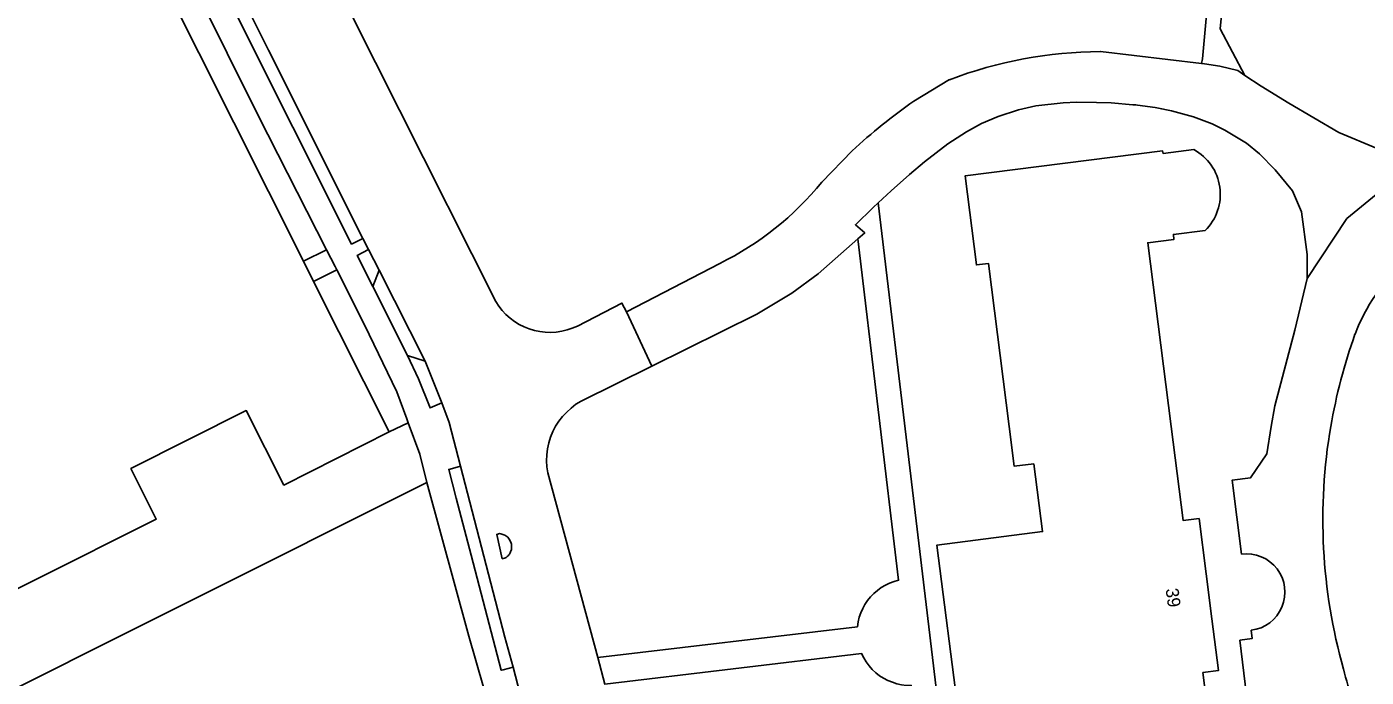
# Model space of a CAD drawing. Extents: x 158132 to 159664, y 385256 to 387218.
# Drawn here: x 159064.7 to 159168.9, y 386480.5 to 386531.1 of the extents above; entities that cross this region are included whole.
import ezdxf

# ---------------------------------------------------------------- set-up
doc = ezdxf.new("R2010")
doc.units = 0
for name, color, linetype in [('IMGEO_Berm_groen', 7, 'Continuous'), ('IMGEO_Groenvoorziening', 7, 'Continuous'), ('IMGEO_Loofbos', 7, 'Continuous'), ('IMGEO_Pand', 7, 'Continuous'), ('IMGEO_Pand_nummerreeks', 7, 'Continuous'), ('IMGEO_Parkeervlak_open', 7, 'Continuous'), ('IMGEO_Rijbaan_lokaal_gesloten', 7, 'Continuous'), ('IMGEO_Rijbaan_lokaal_open', 7, 'Continuous'), ('IMGEO_Verkeerseiland_gesloten', 7, 'Continuous'), ('IMGEO_Voetpad_open', 7, 'Continuous')]:
    doc.layers.add(name, color=color, linetype=linetype)

msp = doc.modelspace()

# ---------------------------------------------------------------- linework, layer by layer
at = {"layer": 'IMGEO_Berm_groen'}
for points in [[(159083.47, 386529.31), (159081.68, 386532.89), (159080.81, 386532.42), (159089.95, 386514.21), (159090.83, 386514.64)], [(159091.26, 386513.79), (159090.38, 386513.33), (159091.61, 386510.9), (159092.08, 386512.17)], [(159095.67, 386505.1), (159094.3, 386505.54), (159095.16, 386503.71), (159096.05, 386501.45), (159096.98, 386501.85)], [(159098.43, 386496.92), (159097.63, 386496.69), (159097.51, 386496.66), (159098.09, 386494.42), (159099.25, 386489.99), (159101.6, 386481.01), (159101.74, 386481.06), (159102.52, 386481.25), (159101.87, 386483.6)]]:
    msp.add_lwpolyline(points, close=True, dxfattribs=at)
at = {"layer": 'IMGEO_Groenvoorziening'}
for points in [[(159148.23, 386529.21), (159156.1, 386528.28), (159156.17, 386528.64), (159157.04, 386538.09), (159157.3, 386540.4), (159141.76, 386542.14), (159126.49, 386544.29), (159130.01, 386573.65), (159146.27, 386576.84)], [(159086.18, 386539.58), (159101.17, 386509.73), (159101.4, 386509.38), (159101.67, 386509.04), (159101.96, 386508.73), (159102.28, 386508.44), (159102.62, 386508.18), (159102.99, 386507.96), (159103.37, 386507.76), (159103.77, 386507.6), (159104.18, 386507.48), (159104.6, 386507.39), (159105.02, 386507.34), (159105.45, 386507.33), (159105.88, 386507.36), (159106.3, 386507.42), (159106.72, 386507.52), (159107.12, 386507.66), (159107.52, 386507.83), (159110.99, 386509.61), (159111.35, 386508.93), (159118.62, 386512.71)], [(159133.72, 386525.35), (159136.49, 386527.02)], [(159159.22, 386490.06), (159158.48, 386495.81), (159159.92, 386496.01), (159161.2, 386497.88), (159161.54, 386500), (159161.8, 386501.6), (159163.38, 386507.51), (159164.32, 386511.52), (159164.33, 386513.4), (159163.9, 386516.72), (159163.2, 386518.37), (159161.85, 386520), (159160.62, 386521.24), (159159.6, 386522.06), (159157.93, 386523.09), (159156.93, 386523.57), (159155.49, 386524.12), (159153.76, 386524.6), (159153.37, 386524.67), (159153.01, 386524.74), (159152.51, 386524.84), (159151.12, 386525.03), (159151, 386525.05), (159150.75, 386525.07), (159149.07, 386525.21), (159147.94, 386525.25), (159146.4, 386525.26), (159145.33, 386525.22), (159143.22, 386524.99), (159141.86, 386524.68), (159140.28, 386524.15), (159138.99, 386523.6), (159137.8, 386522.96), (159136.37, 386522.02), (159134.55, 386520.62), (159133.37, 386519.64), (159131.94, 386518.36), (159130.94, 386517.43), (159139.8, 386443.12)], [(159126.55, 386519.04), (159128.92, 386521.47)], [(159139.52, 386512.71), (159138.58, 386512.59), (159137.7, 386519.52), (159153.08, 386521.47), (159153.11, 386521.28), (159155.5, 386521.58)], [(159156.38, 386515.26), (159153.92, 386514.96), (159153.96, 386514.58), (159151.92, 386514.32), (159153.74, 386500), (159154.68, 386492.67), (159155.92, 386492.83), (159156.46, 386488.53), (159156.91, 386485.02), (159157.42, 386480.99), (159156.22, 386480.84), (159158.99, 386459.1), (159161.05, 386459.36), (159161.1, 386458.96), (159163.46, 386459.26)], [(159137.19, 386477.61), (159135.51, 386490.77), (159143.74, 386491.82), (159143.04, 386497.09), (159141.53, 386496.9), (159141.14, 386500), (159139.52, 386512.71)], [(159057.35, 386422.06), (159076.55, 386431.69), (159094.11, 386440.59), (159110.07, 386448.64), (159110.2, 386448.7), (159111.12, 386449.17), (159111.56, 386449.46), (159111.98, 386449.8), (159112.36, 386450.17), (159112.67, 386450.53), (159110.57, 386454.48), (159107.78, 386460.06), (159105.15, 386465.72), (159102.7, 386471.45), (159101.94, 386473.64), (159099.08, 386483.66), (159095.79, 386495.63), (159058.61, 386477.03)], [(159162.07, 386475.51), (159160.01, 386475.65), (159159.1, 386483.35), (159160.04, 386483.48), (159159.98, 386484.13)], [(159134.79, 386442.58), (159136.74, 386442.71), (159137.91, 386442.87), (159133.51, 386479.83), (159133.13, 386479.84), (159132.76, 386479.89), (159132.39, 386479.96), (159132.04, 386480.08), (159131.69, 386480.22), (159131.36, 386480.39), (159131.05, 386480.59), (159130.75, 386480.82), (159130.48, 386481.08), (159130.23, 386481.35), (159130.01, 386481.66), (159129.81, 386481.98), (159129.64, 386482.31), (159109.67, 386479.93)]]:
    msp.add_lwpolyline(points, dxfattribs=at)
for points in [[(159070.67, 386548.43), (159060.8, 386567.86), (159059.03, 386566.97), (159086.21, 386512.87), (159088, 386513.77), (159082.68, 386524.24)], [(159129.36, 386514.61), (159126.27, 386511.9), (159124.21, 386510.4), (159121.48, 386508.75), (159113.31, 386504.7), (159107.81, 386501.98), (159107.41, 386501.73), (159107.04, 386501.44), (159106.69, 386501.13), (159106.37, 386500.78), (159106.08, 386500.41), (159105.83, 386500.02), (159105.61, 386499.6), (159105.44, 386499.16), (159105.3, 386498.72), (159105.2, 386498.26), (159105.14, 386497.79), (159105.12, 386497.32), (159105.15, 386496.85), (159105.22, 386496.39), (159109.11, 386482.01), (159129.32, 386484.41), (159129.37, 386484.78), (159129.46, 386485.14), (159129.58, 386485.48), (159129.73, 386485.82), (159129.91, 386486.14), (159130.11, 386486.45), (159130.35, 386486.73), (159130.6, 386487), (159130.88, 386487.23), (159131.18, 386487.45), (159131.5, 386487.64), (159131.83, 386487.79), (159132.18, 386487.92), (159132.53, 386488.02)], [(159090.95, 386507.93), (159088.8, 386512.21), (159086.99, 386511.3), (159092.88, 386499.58), (159094.35, 386500.3), (159094.24, 386500.59), (159093.46, 386502.7)]]:
    msp.add_lwpolyline(points, close=True, dxfattribs=at)
for centre, radius, start, end in [((159148.48, 386495.28), 33.93, 90.4295, 110.7037), ((159156.85, 386491.81), 40.74, 124.5982, 133.2841), ((159153.59, 386518.09), 3.98, 314.6535, 61.2893), ((159107.96, 386534.19), 23.98, 296.3821, 320.8034), ((159182.32, 386501.67), 15.3, 56.3026, 158.8201), ((159208.43, 386492.79), 42.87, 160.3649, 170.3228), ((159208.55, 386492.76), 43, 170.3033, 195.7156), ((159159.61, 386487.1), 2.99, 277.0744, 97.4962), ((159190.45, 386486.69), 23.95, 193.4594, 206.0015)]:
    msp.add_arc(centre, radius, start, end, dxfattribs=at)
at = {"layer": 'IMGEO_Loofbos'}
msp.add_lwpolyline([(159158.23, 386537.96), (159157.57, 386530.99), (159159.49, 386527.35), (159160.75, 386526.52), (159162.89, 386525.18), (159166.8, 386522.9), (159169.77, 386521.66), (159174.79, 386520.88), (159178.27, 386521.04), (159176.12, 386524.17), (159174.8, 386526.21), (159181.71, 386526.16), (159187.45, 386525.47), (159190.01, 386519.54), (159192.83, 386518.2)], dxfattribs=at)
at = {"layer": 'IMGEO_Pand'}
for points in [[(159055.65, 386483.24), (159074.74, 386492.79), (159072.77, 386496.72), (159081.74, 386501.24), (159084.68, 386495.44), (159092.88, 386499.58), (159086.99, 386511.3), (159086.21, 386512.87), (159059.03, 386566.97)], [(159155.5, 386521.58), (159153.11, 386521.28), (159153.08, 386521.47), (159137.7, 386519.52), (159138.58, 386512.59), (159139.52, 386512.71), (159141.14, 386500), (159141.53, 386496.9), (159143.04, 386497.09), (159143.74, 386491.82), (159135.51, 386490.77), (159137.19, 386477.61), (159145.42, 386478.66), (159146.15, 386473.48), (159144.64, 386473.29), (159146.66, 386457.42), (159145.54, 386457.28), (159146.41, 386450.43), (159155.18, 386451.54), (159161.99, 386452.41), (159161.94, 386452.84), (159164.51, 386453.16)], [(159156.46, 386488.53), (159155.92, 386492.83), (159154.68, 386492.67), (159153.74, 386500), (159151.92, 386514.32), (159153.96, 386514.58), (159153.92, 386514.96), (159156.38, 386515.26)], [(159163.46, 386459.26), (159161.1, 386458.96), (159161.05, 386459.36), (159158.99, 386459.1), (159156.22, 386480.84), (159157.42, 386480.99), (159156.91, 386485.02), (159156.46, 386488.53)]]:
    msp.add_lwpolyline(points, dxfattribs=at)
msp.add_arc((159153.59, 386518.09), 3.98, 314.6535, 61.2893, dxfattribs=at)
at = {"layer": 'IMGEO_Parkeervlak_open'}
msp.add_lwpolyline([(159092.08, 386512.17), (159091.61, 386510.9), (159094.3, 386505.54), (159095.67, 386505.1)], close=True, dxfattribs=at)
at = {"layer": 'IMGEO_Rijbaan_lokaal_gesloten'}
for points in [[(159166.8, 386522.9), (159162.89, 386525.18), (159160.75, 386526.52), (159159.49, 386527.35), (159158.92, 386527.72), (159157.52, 386528.08), (159156.35, 386528.25), (159156.1, 386528.28), (159148.23, 386529.21)], [(159136.49, 386527.02), (159133.72, 386525.35)], [(159118.62, 386512.71), (159111.35, 386508.93), (159113.31, 386504.7), (159121.48, 386508.75), (159124.21, 386510.4), (159126.27, 386511.9), (159129.36, 386514.61), (159129.89, 386515.08), (159129.16, 386515.72), (159130.54, 386517.05), (159130.94, 386517.43), (159131.94, 386518.36), (159133.37, 386519.64), (159134.55, 386520.62), (159136.37, 386522.02), (159137.8, 386522.96), (159138.99, 386523.6), (159140.28, 386524.15), (159141.86, 386524.68), (159143.22, 386524.99), (159145.33, 386525.22), (159146.4, 386525.26), (159147.94, 386525.25), (159149.07, 386525.21), (159150.75, 386525.07), (159151, 386525.05), (159151.12, 386525.03), (159152.51, 386524.84), (159153.01, 386524.74), (159153.37, 386524.67), (159153.76, 386524.6), (159155.49, 386524.12), (159156.93, 386523.57), (159157.93, 386523.09), (159159.6, 386522.06), (159160.62, 386521.24), (159161.85, 386520), (159163.2, 386518.37), (159163.9, 386516.72), (159164.33, 386513.4), (159164.32, 386511.52), (159167.43, 386516.2), (159171.12, 386519.25)], [(159169.77, 386521.66), (159166.8, 386522.9)], [(159128.92, 386521.47), (159126.55, 386519.04)], [(159181.05, 386521.12), (159178.27, 386521.04), (159174.79, 386520.88), (159171.12, 386519.25), (159167.43, 386516.2), (159164.32, 386511.52), (159163.38, 386507.51), (159161.8, 386501.6), (159161.54, 386500), (159161.2, 386497.88), (159159.92, 386496.01), (159158.48, 386495.81), (159159.22, 386490.06)], [(159159.98, 386484.13), (159160.04, 386483.48), (159159.1, 386483.35), (159160.01, 386475.65), (159162.07, 386475.51)]]:
    msp.add_lwpolyline(points, dxfattribs=at)
for centre, radius, start, end in [((159148.48, 386495.28), 33.93, 90.4295, 110.7037), ((159156.85, 386491.81), 40.74, 124.5982, 133.2841), ((159107.96, 386534.19), 23.98, 296.3821, 320.8034), ((159182.32, 386501.67), 15.3, 56.3026, 158.8201), ((159208.43, 386492.79), 42.87, 160.3649, 170.3228), ((159208.55, 386492.76), 43, 170.3033, 195.7156), ((159159.61, 386487.1), 2.99, 277.0744, 97.4962), ((159190.45, 386486.69), 23.95, 193.4594, 206.0015)]:
    msp.add_arc(centre, radius, start, end, dxfattribs=at)
at = {"layer": 'IMGEO_Rijbaan_lokaal_open'}
for points in [[(159109.67, 386479.93), (159109.11, 386482.01), (159105.22, 386496.39), (159105.15, 386496.85), (159105.12, 386497.32), (159105.14, 386497.79), (159105.2, 386498.26), (159105.3, 386498.72), (159105.44, 386499.16), (159105.61, 386499.6), (159105.83, 386500.02), (159106.08, 386500.41), (159106.37, 386500.78), (159106.69, 386501.13), (159107.04, 386501.44), (159107.41, 386501.73), (159107.81, 386501.98), (159113.31, 386504.7), (159111.35, 386508.93), (159110.99, 386509.61), (159107.52, 386507.83), (159107.12, 386507.66), (159106.72, 386507.52), (159106.3, 386507.42), (159105.88, 386507.36), (159105.45, 386507.33), (159105.02, 386507.34), (159104.6, 386507.39), (159104.18, 386507.48), (159103.77, 386507.6), (159103.37, 386507.76), (159102.99, 386507.96), (159102.62, 386508.18), (159102.28, 386508.44), (159101.96, 386508.73), (159101.67, 386509.04), (159101.4, 386509.38), (159101.17, 386509.73), (159086.18, 386539.58)], [(159081.68, 386532.89), (159083.47, 386529.31), (159090.83, 386514.64), (159091.26, 386513.79), (159092.08, 386512.17), (159095.67, 386505.1), (159096.98, 386501.85), (159097.53, 386500.31), (159098.43, 386496.92), (159101.87, 386483.6), (159102.52, 386481.25), (159103.08, 386479.14)]]:
    msp.add_lwpolyline(points, dxfattribs=at)
msp.add_lwpolyline([(159102.06, 386489.87), (159101.99, 386489.81), (159101.92, 386489.76), (159101.67, 386489.7), (159101.24, 386491.59), (159101.46, 386491.66), (159101.55, 386491.64), (159101.64, 386491.62), (159101.72, 386491.6), (159101.8, 386491.57), (159101.88, 386491.53), (159101.96, 386491.48), (159102.03, 386491.43), (159102.1, 386491.37), (159102.15, 386491.3), (159102.21, 386491.23), (159102.26, 386491.16), (159102.3, 386491.08), (159102.34, 386491), (159102.36, 386490.92), (159102.39, 386490.83), (159102.4, 386490.74), (159102.4, 386490.66), (159102.4, 386490.57), (159102.39, 386490.48), (159102.38, 386490.39), (159102.35, 386490.31), (159102.32, 386490.23), (159102.28, 386490.15), (159102.24, 386490.07), (159102.18, 386490), (159102.13, 386489.93)], close=True, dxfattribs=at)
at = {"layer": 'IMGEO_Verkeerseiland_gesloten'}
msp.add_lwpolyline([(159101.46, 386491.66), (159101.24, 386491.59), (159101.67, 386489.7), (159101.92, 386489.76), (159101.99, 386489.81), (159102.06, 386489.87), (159102.13, 386489.93), (159102.18, 386490), (159102.24, 386490.07), (159102.28, 386490.15), (159102.32, 386490.23), (159102.35, 386490.31), (159102.38, 386490.39), (159102.39, 386490.48), (159102.4, 386490.57), (159102.4, 386490.66), (159102.4, 386490.74), (159102.39, 386490.83), (159102.36, 386490.92), (159102.34, 386491), (159102.3, 386491.08), (159102.26, 386491.16), (159102.21, 386491.23), (159102.15, 386491.3), (159102.1, 386491.37), (159102.03, 386491.43), (159101.96, 386491.48), (159101.88, 386491.53), (159101.8, 386491.57), (159101.72, 386491.6), (159101.64, 386491.62), (159101.55, 386491.64)], close=True, dxfattribs=at)
at = {"layer": 'IMGEO_Voetpad_open'}
for points in [[(159070.67, 386548.43), (159082.68, 386524.24), (159088, 386513.77), (159088.66, 386512.47), (159088.8, 386512.21), (159090.95, 386507.93), (159093.46, 386502.7), (159094.24, 386500.59), (159094.35, 386500.3), (159095.26, 386497.85), (159095.79, 386495.63), (159099.08, 386483.66), (159101.94, 386473.64)], [(159103.08, 386479.14), (159102.52, 386481.25), (159101.74, 386481.06), (159101.6, 386481.01), (159099.25, 386489.99), (159098.09, 386494.42), (159097.51, 386496.66), (159097.63, 386496.69), (159098.43, 386496.92), (159097.53, 386500.31), (159096.98, 386501.85), (159096.05, 386501.45), (159095.16, 386503.71), (159094.3, 386505.54), (159091.61, 386510.9), (159090.38, 386513.33), (159091.26, 386513.79), (159090.83, 386514.64), (159089.95, 386514.21), (159080.81, 386532.42)], [(159139.8, 386443.12), (159130.94, 386517.43), (159130.54, 386517.05), (159129.16, 386515.72), (159129.89, 386515.08), (159129.36, 386514.61), (159132.53, 386488.02), (159132.18, 386487.92), (159131.83, 386487.79), (159131.5, 386487.64), (159131.18, 386487.45), (159130.88, 386487.23), (159130.6, 386487), (159130.35, 386486.73), (159130.11, 386486.45), (159129.91, 386486.14), (159129.73, 386485.82), (159129.58, 386485.48), (159129.46, 386485.14), (159129.37, 386484.78), (159129.32, 386484.41), (159109.11, 386482.01), (159109.67, 386479.93), (159129.64, 386482.31), (159129.81, 386481.98), (159130.01, 386481.66), (159130.23, 386481.35), (159130.48, 386481.08), (159130.75, 386480.82), (159131.05, 386480.59), (159131.36, 386480.39)], [(159058.61, 386477.03), (159095.79, 386495.63), (159095.26, 386497.85), (159094.35, 386500.3), (159092.88, 386499.58), (159084.68, 386495.44), (159081.74, 386501.24), (159072.77, 386496.72), (159074.74, 386492.79), (159055.65, 386483.24)]]:
    msp.add_lwpolyline(points, dxfattribs=at)
for points in [[(159157.57, 386530.99), (159158.23, 386537.96), (159158.49, 386540.26), (159157.3, 386540.4), (159157.04, 386538.09), (159156.17, 386528.64), (159156.1, 386528.28), (159156.35, 386528.25), (159157.52, 386528.08), (159158.92, 386527.72), (159159.49, 386527.35)], [(159088, 386513.77), (159086.21, 386512.87), (159086.99, 386511.3), (159088.8, 386512.21), (159088.66, 386512.47)]]:
    msp.add_lwpolyline(points, close=True, dxfattribs=at)

# ---------------------------------------------------------------- texts
at = {"layer": 'IMGEO_Pand_nummerreeks'}
msp.add_text('39', height=1, rotation=277.6201, dxfattribs=at).set_placement((159153.31, 386487.34))

doc.saveas('drawing.dxf')
